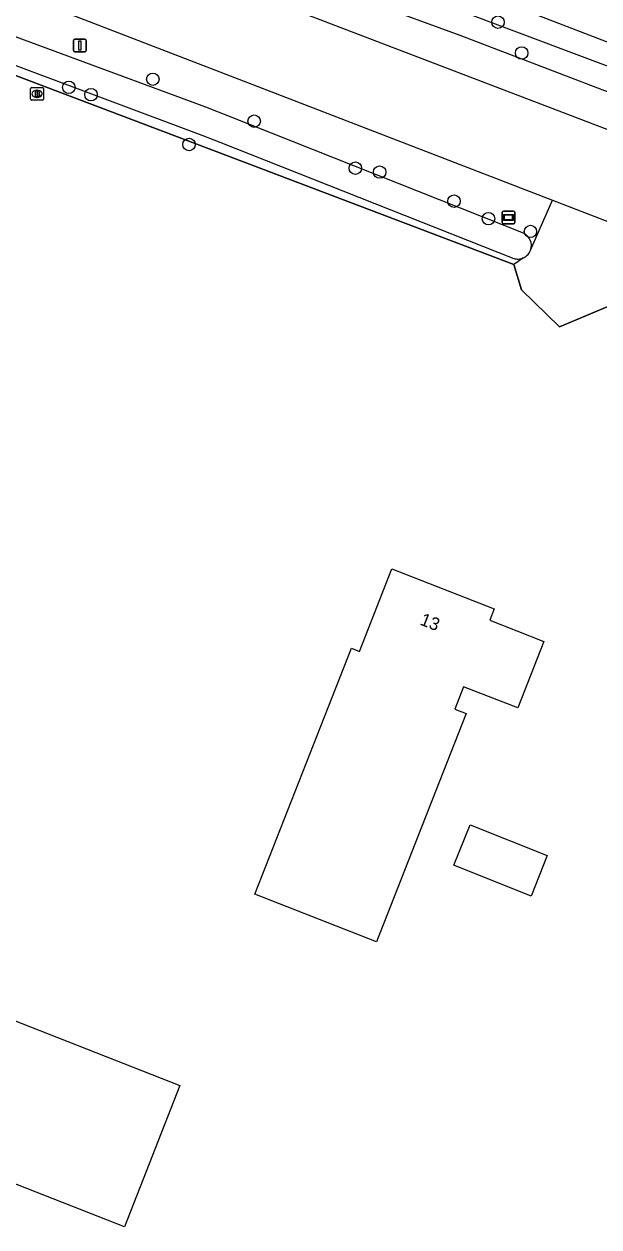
# Model space of a CAD drawing. Extents: x 155209 to 156823, y 385356 to 388482.
# Drawn here: x 155769.5 to 155814.6, y 386616.1 to 386710.5 of the extents above; entities that cross this region are included whole.
import ezdxf

# ---------------------------------------------------------------- set-up
doc = ezdxf.new("R2010")
doc.units = 0
for name, color, linetype in [('IMGEO_Afsluitpaal', 7, 'Continuous'), ('IMGEO_Boom', 7, 'Continuous'), ('IMGEO_Brandkraan', 7, 'Continuous'), ('IMGEO_Fietspad_gesloten', 7, 'Continuous'), ('IMGEO_Groenvoorziening', 7, 'Continuous'), ('IMGEO_Hek', 7, 'Continuous'), ('IMGEO_Pand', 7, 'Continuous'), ('IMGEO_Pand_nummerreeks', 7, 'Continuous'), ('IMGEO_Rijbaan_lokaal_gesloten', 7, 'Continuous'), ('IMGEO_Verklikker', 7, 'Continuous'), ('IMGEO_Voetpad_gesloten', 7, 'Continuous'), ('IMGEO_Waterloop', 7, 'Continuous')]:
    doc.layers.add(name, color=color, linetype=linetype)

msp = doc.modelspace()

# ---------------------------------------------------------------- linework, layer by layer
at = {"layer": 'IMGEO_Afsluitpaal'}
for p, q in [((155773.401, 386708.38), (155773.401, 386709.18)), ((155773.401, 386709.18), (155773.401, 386708.38)), ((155773.501, 386709.28), (155774.291, 386709.28)), ((155774.291, 386709.28), (155773.501, 386709.28)), ((155774.391, 386709.18), (155774.391, 386708.38)), ((155774.391, 386708.38), (155774.391, 386709.18)), ((155774.291, 386708.28), (155773.501, 386708.28)), ((155773.501, 386708.28), (155774.291, 386708.28))]:
    msp.add_line(p, q, dxfattribs=at)
msp.add_lwpolyline([(155773.821, 386709.155), (155773.971, 386709.155), (155773.971, 386708.405), (155773.821, 386708.405), (155773.821, 386709.155)], dxfattribs=at)
for centre, start, end in [((155773.501, 386709.18), 90, 180), ((155773.501, 386709.18), 90, 180), ((155774.291, 386709.18), 0, 90), ((155774.291, 386709.18), 360, 90), ((155773.501, 386708.38), 180, 270), ((155773.501, 386708.38), 180, 270), ((155774.291, 386708.38), 270, 0), ((155774.291, 386708.38), 270, 0)]:
    msp.add_arc(centre, 0.1, start, end, dxfattribs=at)
at = {"layer": 'IMGEO_Boom'}
for centre in [(155806.699, 386710.608), (155808.558, 386708.188), (155779.618, 386706.13), (155773.035, 386705.491), (155774.765, 386704.92), (155787.573, 386702.838), (155782.461, 386701.013), (155795.513, 386699.147), (155797.412, 386698.845), (155803.252, 386696.564), (155805.954, 386695.188), (155809.245, 386694.188)]:
    msp.add_circle(centre, 0.489, dxfattribs=at)
at = {"layer": 'IMGEO_Brandkraan'}
for p, q in [((155770.037, 386704.56), (155770.037, 386705.412)), ((155770.112, 386705.486), (155770.964, 386705.486)), ((155770.525, 386705.266), (155770.55, 386705.266)), ((155771.038, 386705.412), (155771.038, 386704.56)), ((155770.964, 386704.486), (155770.112, 386704.486)), ((155770.548, 386704.706), (155770.523, 386704.706))]:
    msp.add_line(p, q, dxfattribs=at)
for points in [[(155770.037, 386704.56), (155770.037, 386705.412)], [(155770.112, 386705.486), (155770.964, 386705.486)], [(155770.385, 386705.186), (155770.385, 386704.786), (155770.598, 386704.786)], [(155770.616, 386705.186), (155770.385, 386705.186)], [(155771.038, 386705.412), (155771.038, 386704.56)], [(155770.964, 386704.486), (155770.112, 386704.486)], [(155770.564, 386705.105), (155770.51, 386705.105), (155770.51, 386705.029)], [(155770.51, 386705.029), (155770.563, 386705.029)], [(155770.572, 386704.953), (155770.51, 386704.953), (155770.51, 386704.872)], [(155770.51, 386704.872), (155770.572, 386704.872)]]:
    msp.add_lwpolyline(points, dxfattribs=at)
for centre, radius, start, end in [((155770.114, 386705.41), 0.0765, 91.55205, 178.44795), ((155770.114, 386705.41), 0.0765, 91.55205, 178.44795), ((155770.62, 386705.041), 0.145, 59.4692, 91.53667), ((155770.645, 386705.088), 0.0922, 285.51372, 58.15012), ((155770.962, 386705.41), 0.0765, 1.55205, 88.44795), ((155770.962, 386705.41), 0.0765, 1.55205, 88.44795), ((155770.114, 386704.562), 0.0765, 181.55205, 268.44795), ((155770.114, 386704.562), 0.0765, 181.55205, 268.44795), ((155770.565, 386705.067), 0.0379, 267.82845, 90.93552), ((155770.573, 386704.912), 0.0404, 269.87594, 90.50774), ((155770.604, 386705.037), 0.251, 268.66757, 293.53466), ((155770.65, 386704.896), 0.105, 301.31148, 78.98903), ((155770.962, 386704.562), 0.0765, 271.55205, 358.44795), ((155770.962, 386704.562), 0.0765, 271.55205, 358.44795)]:
    msp.add_arc(centre, radius, start, end, dxfattribs=at)
for centre, major_axis, ratio, start_param, end_param in [((155770.524, 386704.986), (-0.387, 0.002), 0.722429, 4.712389, 7.853982), ((155770.549, 386704.986), (-0.39, 0.002), 0.717154, 1.570796, 4.712389)]:
    msp.add_ellipse(centre, major_axis=major_axis, ratio=ratio, start_param=start_param, end_param=end_param, dxfattribs=at)
at = {"layer": 'IMGEO_Fietspad_gesloten'}
msp.add_lwpolyline([(155783.255, 386721.411), (155791.391, 386718.27), (155821.976, 386706.464)], dxfattribs=at)
at = {"layer": 'IMGEO_Groenvoorziening'}
msp.add_lwpolyline([(155807.945, 386691.605), (155784.597, 386700.457), (155766.422, 386707.347), (155764.802, 386707.961)], dxfattribs=at)
at = {"layer": 'IMGEO_Hek'}
for points in [[(155766.422, 386707.347), (155784.597, 386700.457)], [(155784.597, 386700.457), (155807.945, 386691.605)], [(155807.945, 386691.605), (155808.555, 386689.616), (155811.529, 386686.692), (155815.753, 386688.468)]]:
    msp.add_lwpolyline(points, dxfattribs=at)
at = {"layer": 'IMGEO_Pand'}
for points in [[(155793.383, 386656.83), (155795.209, 386661.484), (155795.839, 386661.237), (155798.379, 386667.711), (155806.398, 386664.565), (155806.055, 386663.69), (155810.306, 386662.022), (155808.256, 386656.798), (155804.005, 386658.465), (155803.31, 386656.694), (155804.191, 386656.348), (155802.365, 386651.694), (155797.165, 386638.443), (155787.635, 386642.182), (155793.383, 386656.83)], [(155803.239, 386644.458), (155804.515, 386647.636), (155810.567, 386645.205), (155809.291, 386642.027), (155803.239, 386644.458)], [(155749.509, 386627.012), (155753.882, 386638.101), (155781.743, 386627.167), (155777.389, 386616.071), (155749.509, 386627.012)]]:
    msp.add_lwpolyline(points, dxfattribs=at)
at = {"layer": 'IMGEO_Rijbaan_lokaal_gesloten'}
for points in [[(155761.509, 386715.74), (155786.697, 386706.017), (155810.968, 386696.648)], [(155818.26, 386701.023), (155787.542, 386712.8)], [(155810.968, 386696.648), (155818.432, 386693.767)]]:
    msp.add_lwpolyline(points, dxfattribs=at)
at = {"layer": 'IMGEO_Verklikker'}
for p, q in [((155807.026, 386694.89), (155807.026, 386695.69)), ((155807.026, 386695.69), (155807.026, 386694.89)), ((155807.126, 386695.79), (155807.916, 386695.79)), ((155807.916, 386695.79), (155807.126, 386695.79)), ((155808.016, 386695.69), (155808.016, 386694.89)), ((155808.016, 386694.89), (155808.016, 386695.69)), ((155807.916, 386694.79), (155807.126, 386694.79)), ((155807.126, 386694.79), (155807.916, 386694.79))]:
    msp.add_line(p, q, dxfattribs=at)
for points in [[(155807.127, 386695.522), (155807.915, 386695.522), (155807.915, 386695.058), (155807.127, 386695.058), (155807.127, 386695.522)], [(155807.192, 386695.457), (155807.192, 386695.123), (155807.85, 386695.123), (155807.85, 386695.457), (155807.192, 386695.457)]]:
    msp.add_lwpolyline(points, dxfattribs=at)
for centre, start, end in [((155807.126, 386695.69), 90, 180), ((155807.126, 386695.69), 90, 180), ((155807.916, 386695.69), 0, 90), ((155807.916, 386695.69), 360, 90), ((155807.126, 386694.89), 180, 270), ((155807.126, 386694.89), 180, 270), ((155807.916, 386694.89), 270, 0), ((155807.916, 386694.89), 270, 0)]:
    msp.add_arc(centre, 0.1, start, end, dxfattribs=at)
at = {"layer": 'IMGEO_Voetpad_gesloten'}
for points in [[(155809.254, 386692.725), (155810.968, 386696.648)], [(155808.673, 386692.105), (155808.361, 386691.891), (155807.945, 386691.605)], [(155808.673, 386692.105), (155808.764, 386692.149), (155808.845, 386692.199), (155808.922, 386692.256), (155808.993, 386692.319), (155809.059, 386692.389), (155809.118, 386692.464), (155809.169, 386692.544), (155809.214, 386692.629), (155809.254, 386692.725)], [(155815.753, 386688.468), (155811.529, 386686.692), (155808.555, 386689.616), (155807.945, 386691.605)]]:
    msp.add_lwpolyline(points, dxfattribs=at)
at = {"layer": 'IMGEO_Waterloop'}
for points in [[(155785.566, 386717.88), (155790.567, 386716.128), (155803.207, 386711.701), (155818.456, 386705.974), (155817.551, 386704.278), (155803.725, 386709.57), (155789.982, 386714.61), (155785.106, 386716.398)], [(155808.696, 386694.055), (155785.631, 386703.195), (155783.773, 386703.931), (155761.11, 386712.301), (155761.066, 386712.319)], [(155760.196, 386710.46), (155783.453, 386701.746), (155784.872, 386701.185), (155807.931, 386692.065), (155808.023, 386692.041), (155808.118, 386692.025), (155808.213, 386692.017), (155808.308, 386692.018), (155808.403, 386692.028), (155808.497, 386692.046), (155808.589, 386692.072), (155808.673, 386692.105)]]:
    msp.add_lwpolyline(points, dxfattribs=at)
msp.add_arc((155808.251, 386693.086), 1.066, 340.18324, 65.33762, dxfattribs=at)

# ---------------------------------------------------------------- texts
at = {"layer": 'IMGEO_Pand_nummerreeks'}
msp.add_text('13', height=1, rotation=338.57902, dxfattribs=at).set_placement((155800.506, 386663.353))

doc.saveas('drawing.dxf')
